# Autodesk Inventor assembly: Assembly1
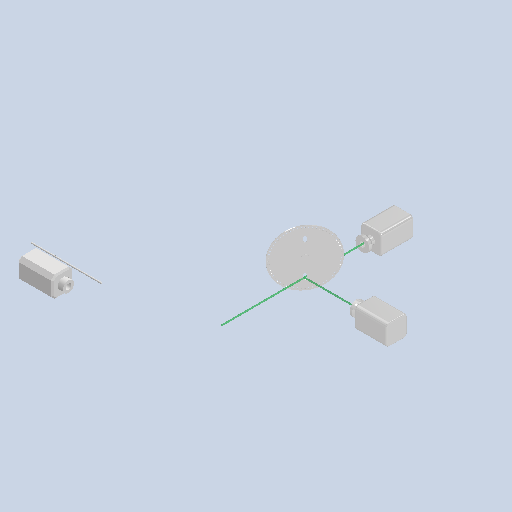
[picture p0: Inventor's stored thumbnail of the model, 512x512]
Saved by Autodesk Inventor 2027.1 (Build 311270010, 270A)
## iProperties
Created: 2026-07
Part Number: Assembly1
Document SubType Name: Assembly
Designer: dunge
Author: dunge
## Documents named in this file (7)
- C:\Users\dunge\OneDrive\Documents\Inventor\Inventor\Inventor\simplified-drawings\figure-1c.iam
- C:\Users\dunge\OneDrive\Documents\Inventor\Inventor\Inventor\simplified-drawings\chopper-simple.ipt
- C:\Users\dunge\OneDrive\Documents\Inventor\Inventor\Inventor\simplified-drawings\generic-beam.ipt
- C:\Users\dunge\OneDrive\Documents\Inventor\Inventor\Inventor\simplified-drawings\emitter-simple.ipt
- C:\Users\dunge\OneDrive\Documents\Inventor\Inventor\Inventor\simplified-drawings\collector-simple.ipt
- C:\Users\dunge\OneDrive\Documents\Inventor\Inventor\Inventor\simplified-drawings\generic-beam-shorter.ipt
- C:\Users\dunge\OneDrive\Documents\Inventor\Inventor\Inventor\simplified-drawings\plane.ipt
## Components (8 placed, 6 different names)
1. chopper-simple:1 — Tangent:1
2. generic-beam:1 — Mate:6
3. emitter-simple:1
4. collector-simple:1 — Mate:5, Mate:6
5. collector-simple:2 — Mate:3, Flush:1, Flush:2, Mate:4, Angle:1
6. generic-beam-shorter:1 — Mate:4, Angle:1
7. plane:1 — Mate:3, Flush:1, Flush:2, Tangent:1, Mate:5
8. generic-beam-shorter:2
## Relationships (8: Mate 4, Flush 2, Angle 1, Tangent 1)
- Mate:3: collector-simple:2 ↔ plane:1
- Flush:1: collector-simple:2 ↔ plane:1
- Flush:2: collector-simple:2 ↔ plane:1
- Mate:4: collector-simple:2 ↔ generic-beam-shorter:1
- Angle:1: collector-simple:2 ↔ generic-beam-shorter:1
- Tangent:1: chopper-simple:1 ↔ plane:1
- Mate:5: collector-simple:1 ↔ plane:1
- Mate:6: generic-beam:1 ↔ collector-simple:1
## Named parameters: Finish4_Area = 82.84667 mm, Finish5_Area = 662.56225 mm, Finish6_Area = 421.26303 mm
